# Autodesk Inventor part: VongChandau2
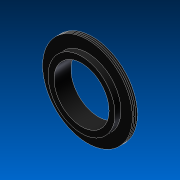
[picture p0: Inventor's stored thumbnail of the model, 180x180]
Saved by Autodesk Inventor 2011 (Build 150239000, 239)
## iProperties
Created: 2011-05
Part Number: VongChandau2
Document SubType Name: Modeling
Designer: 904Chiaki
Density: 1 g/cm^3
Mass: 53.4941 g
Surface Area: 225.023 cm^2
Volume: 53.4941 cm^3
Author: 904Chiaki
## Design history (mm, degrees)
sketch "Sketch1"
  geometry: L1 (-5.835, 18.205)-(-5.835, -16.433); L2 (26.665, 9.18)-(26.665, -10.82); L3 (26.665, 9.18)-(33.665, 9.18); L4 (26.665, -10.82)-(33.665, -10.82); L5 (33.665, 2.18)-(47.165, 2.18); L6 (47.165, -3.82)-(33.665, -3.82); L7 (47.165, 2.18)-(45.433, 1.18); L8 (47.165, 0.18)-(45.433, 1.18); L9 (47.165, 0.18)-(45.433, -0.82); L10 (45.433, -0.82)-(47.165, -1.82); L11 (47.165, -1.82)-(45.433, -2.82); L12 (45.433, -2.82)-(47.165, -3.82); L13 (33.665, -10.82)-(33.665, -3.82); L14 (33.665, 2.18)-(33.665, 9.18); 1 further point
  constraints: 28 end point
  dimensions: "d0" = 32.5 distance between parallel lines of L1 L2; "d1" = 20 distance of L2.start L2.end; "d2" = 7 distance of L2.start L3.end; "d6" = 30 deg angle of L5 L7
revolve "Revolution1" sketch "Sketch1" stored, may be unused: angle "d11" = 90 deg
body "Solid1"
